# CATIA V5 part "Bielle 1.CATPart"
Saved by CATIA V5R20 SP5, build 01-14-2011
Part number: Bielle 1
Bounding box of the stored display mesh (mm): x -220 to 220, y -14.191 to 109.915, z 0 to 93.978
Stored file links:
  F:\Travaux\Modélisations\CFAO_2011\MMS\MMS_GR2\AA_OK\tquattrone\Catia\Bielle 1.CATPart
  C:\Users\Tom\Documents\Cours 2A\CFAO\Projet thinkmotion\Aileron_citroen.CATProduct
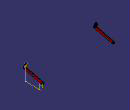
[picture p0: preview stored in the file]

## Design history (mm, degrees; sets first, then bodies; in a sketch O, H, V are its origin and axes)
Parameters
  Epaisseur_bielle_1 = 5 mm
  Diametre_trou_bielle_1 = 6 mm
Set1
  Plane1 "Plan_bielle1": linked copy from another document
  Point1 "Point_bielle_11": linked copy from another document
  Point2 "Point_bielle_12": linked copy from another document
  Plane2 "Plan_sym": linked copy from another document
Body1 (main body)
  Sketch1 on Plane1, origin (220, 0, 0), H (0, 1, 0), V (0, 0, 1)
    line L1 (-4.5034, 89.8277) -> (-11.8441, 67.9545)
    arc A1 centre (-9, 67) radius 3 from (-11.8441, 67.9545) to (-6.1559, 66.0455) ccw
    point P3 (-9, 67)
    line L2 (-6.1559, 66.0455) -> (1.1848, 87.9187)
    arc A2 centre (-1.6593, 88.8732) radius 3 from (1.1848, 87.9187) to (-4.5034, 89.8277) ccw
    reference projected point E1 (-9, 67) from Point2
    point P7 (3.7081, 87.0933)
    line L3 (3.7081, 87.0933) -> (0, 75.3085)
    point P8 (0, 75.3085)
    arc A3 centre (3.333, 74.2598) radius 3.4941 from (0, 75.3085) to (2.7481, 70.8149) ccw
    line L4 (2.7481, 70.8149) -> (105.3502, 46.759)
    arc A4 centre (104, 41) radius 5.9151 from (105.3502, 46.759) to (102.6498, 35.241) cw
    point P12 (104, 41)
    line L5 (102.6498, 35.241) -> (-9.6783, 61.931)
    arc A5 centre (-8.3207, 67.6447) radius 5.8728 from (-9.6783, 61.931) to (-13.7054, 69.9889) cw
    line L6 (-13.7054, 69.9889) -> (-6.4887, 90.491)
    arc A6 centre (-1.4189, 88.7064) radius 5.3747 from (-6.4887, 90.491) to (3.7081, 87.0933) cw
    point P19 (3.7081, 87.0933)
    reference projected point E2 (104, 41) from Point1
    circle A7 centre (104, 41) radius 3
    point P20 (104, 41)
    reference projected point E3 (104, 41) from Point1
    radius A7 = 3 {= Diametre_trou_bielle_1 /2}
    distance L2 L1 = 6 {= Diametre_trou_bielle_1}
    tangency: A1 L1, L2 A1, A2 L1, A2 L2, A3 L3, A4 L4, A5 L5, A6 L3, A6 L6
    coincidence: P3 E1, P8 V, P12 E2, P19 P7, P20 E3
  Pad1: profile Sketch1, direction (-1, 0, 0), length 5 {= Epaisseur_bielle_1}
  Mirror1: of the body so far, about Plane2
  Sketch2 on start face of Pad1, origin (220, 0, 0), H (0, 1, 0), V (0, 0, 1)
    line L1 (-9, 67) -> (-1.6593, 88.8732)
    point P1 (-9, 67)
    point P2 (-1.6593, 88.8732)
    reference projected arc E1 centre (-1.6593, 88.8732) radius 3 from (1.1848, 87.9187) to (-4.5034, 89.8277) ccw from edge [start face of Pad1 | face of Pad1 from Sketch1.A2]
    reference projected arc E2 centre (-9, 67) radius 3 from (-11.8441, 67.9545) to (-6.1559, 66.0455) ccw from edge [start face of Pad1 | face of Pad1 from Sketch1.A1]
    distance P2 E1 = 3
    distance P1 E2 = 3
